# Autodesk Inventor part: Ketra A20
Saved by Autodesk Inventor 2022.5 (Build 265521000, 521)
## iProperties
Created: 2024-07
Part Number: Ketra A20
Material: Generic
Document SubType Name: Modeling
Designer: AdminForWorker
Density: 1 g/cm^3
Appearance: Default
Title: Ketra A20
Author: AdminForWorker
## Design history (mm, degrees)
feature "Body1"
body "Solid1"
